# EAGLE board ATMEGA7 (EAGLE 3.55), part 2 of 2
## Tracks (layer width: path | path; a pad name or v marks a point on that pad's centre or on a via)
0V
  Top 0.33: JP4. 20.45,10.76 21.09,10.76 21.09,12.67 21.41,12.98 21.73,12.98 21.73,17.11 22.04,17.43 30.3,17.43 30.9,17.3
  Bottom 0.33: 30.9,17.3 30.93,16.48 34.11,16.48 35.05,16.35 35.38,15.53 35.38,14.26 42.36,14.26 42.68,14.57 42.68,17.43 45.85,17.43 46.65,17.3 46.81,16.48 49.98,16.48 50.8,16.35 51.25,15.53 51.25,14.26 58.24,14.26 58.55,14.57 58.55,17.43 61.73,17.43 62.35,17.3 62.37,16.48 65.54,16.48 66.5,16.35 66.81,15.53 66.81,14.26 74.11,14.26 74.43,14.57 74.43,17.43 77.29,17.43 78.12,17.3 78.24,16.48 81.42,16.48 82.28,16.35 82.69,15.53 82.69,14.26 89.67,14.26 89.99,14.57 89.99,17.43 93.16,17.43 93.88,17.3 93.8,16.48 97.29,16.48 98.03,16.35 98.56,15.53 98.56,14.26 105.55,14.26 105.86,14.57 105.86,17.43 109.04,17.43 109.6,17.3 109.67,16.48 112.85,16.48 113.75,16.35 114.12,15.53 114.12,14.26 121.42,14.26 121.74,14.57 121.74,17.43 124.59,17.43 125.4,17.3 125.55,16.48 128.72,16.48 129.55,16.35 129.99,15.53 129.99,14.57 130.31,14.26 136.66,14.26 136.66,17.11 136.98,17.43 140.47,17.43 141.1,17.3 141.1,16.48 144.28,16.48 145.25,16.35
+3V  (via drill 0.61 pad 1.02)
  Top 0.33: 53.16,40.92 53.79,41.24 53.79,52.67 54.11,52.99 54.43,52.99 54.43,53.94 54.11,54.26 54.11,54.58 53.79,54.9 53.79,55.85 53.16,56.16 53.16,56.8 53.16,65.69 55.7,65.69 56.42,65.96 | 38.55,31.4 38.55,29.18 38.6,28.33 | 38.55,31.4 v38.55,40.61 38.87,40.92 38.87,50.77 42.36,50.77 43,51.09 | 38.55,31.4 42.68,31.4 QG1. | 45.54,51.09 46.17,51.4 48.4,51.4 48.4,51.72 48.71,52.04 48.71,52.35 49.03,52.67 49.03,52.99 49.35,53.31 49.35,54.26 49.66,54.26 49.98,54.58 49.98,55.85 IC6. 50.62,56.8 v50.62,61.56
  Bottom 0.33: R10. 55.06,62.83 53.79,62.83 R11. 52.52,62.2 52.52,61.56 v50.62,61.56 34.74,61.56 34.42,61.24 34.42,57.75 34.45,56.7 34.42,55.85 33.79,55.85 | 33.79,55.85 33.79,53.94 29.34,53.94 29.34,51.72 29.66,51.4 35.38,51.4 35.38,49.5 36.97,49.5 38,49.66 | 33.79,55.85 33.65,56.7 | IC6. 53.16,56.16 | 43,51.09 45.54,51.09 45.85,50.45 56.33,50.45 56.65,50.13 57.6,50.13 57.92,49.81 58.87,49.81 58.87,50.13 59.19,50.45 60.46,50.45 60.78,51.09 | 53.24,31.33 52.52,30.77 52.52,30.13 46.49,30.13 46.17,30.45 46.17,31.08 43.95,31.08 QG1. | v38.55,40.61 36.01,40.61 R12.
+5V  (via drill 0.61 pad 1.02)
  Top 0.33: v26.17,13.94 26.49,13.62 26.49,12.67 26.8,12.35 v26.8,10.13
  Bottom 0.33: v26.17,13.94 25.85,14.26 20.14,14.26 20.14,13.62 19.68,12.98 | v26.8,10.13 28.39,10.13 29.03,10.06 29.66,10.13 31.25,10.13 R1. 32.52,10.13 34.42,10.13 34.74,9.81 35.38,9.81 35.7,10.13 43.95,10.13 44.59,10.06 45.22,10.13 46.81,10.13 R3. 48.08,10.13 49.98,10.13 50.3,9.81 51.25,9.81 51.57,10.13 59.83,10.13 60.46,10.06 61.09,10.13 62.37,10.13 R18. 63.64,10.13 65.86,10.13 66.17,9.81 66.81,9.81 67.13,10.13 75.7,10.13 76.33,10.06 76.97,10.13 78.24,10.13 R19. 79.51,9.81 82.69,9.81 83,10.13 91.58,10.13 92.21,10.06 92.84,10.13 94.11,10.13 R20. 95.39,10.13 97.29,10.13 97.61,9.81 98.56,9.81 98.88,10.13 107.13,10.13 107.77,10.06 108.4,10.13 109.67,10.13 R21. 110.94,10.13 112.85,10.13 113.17,9.81 114.12,9.81 114.44,10.13 123.01,10.13 123.64,10.06 124.28,10.13 125.55,10.13 R22. 126.82,9.81 129.99,9.81 130.31,10.13 138.88,10.13 139.52,10.06 140.15,10.13 141.42,10.13 R23.
+12V  (via drill 0.61 pad 1.02)
  Top 0.33: 112.85,80.18 112.21,79.66 112.21,79.98
  Top 0.406: 115.7,71.72 130.31,71.72 130.31,73.63 136.98,73.63 136.98,71.11 | 136.98,71.11 136.98,71.09 | 136.98,71.11 136.97,71.11
  Top 0.813: 112.85,79.98 112.21,79.98 109.67,79.98 109.67,80.3 115.7,80.3 115.7,71.72 50.94,71.72 | CON6. 10.93,80.3 v23.63,80.3 | v28.71,80.3 39.51,80.3 39.51,71.72 50.94,71.72 | 50.94,71.72 50.62,71.72
  Bottom 0.813: v23.63,80.3 v28.71,80.3
+15V
  Top 0.813: IC11. 95.7,84.42 103.32,84.42 JP5. 106.5,84.11 106.5,82.52 | 106.5,82.52 106.5,80.5 | 106.5,82.52 IC10.
-12V
  Top 0.33: 139.52,81.56 139.52,79.34 139.51,78.73
  Bottom 0.33: 153.48,77.46 153.17,76.8 140.15,76.8 139.84,77.12 139.84,78.07 139.51,78.73
A0  (via drill 0.61 pad 1.02)
  Top 0.33: v160.47,39.34 160.47,30.77 163.33,30.77 163.33,30.45 163.65,30.13 163.65,29.81 164.28,29.81 164.92,29.5 | v136.03,40.92 135.71,41.24 135.71,56.8 136.03,57.12 v136.66,57.12
  Bottom 0.33: 105.75,56.8 108.4,56.8 108.4,56.16 108.72,55.85 109.67,55.85 109.99,56.16 120.78,56.16 121.1,55.85 123.01,55.85 123.01,56.16 123.33,56.48 132.85,56.48 132.85,57.12 135.02,57.12 v136.66,57.12 | v160.47,39.34 160.16,39.66 137.93,39.66 137.61,39.97 137.61,40.92 v136.03,40.92
A1  (via drill 0.61 pad 1.02)
  Top 0.33: v139.52,32.35 v139.52,41.88 v139.52,52.35 | v103.96,55.85 106.18,55.85 v106.18,40.61
  Bottom 0.33: v139.52,52.35 136.34,52.35 136.03,52.67 133.8,52.67 133.49,52.99 132.22,52.99 132.22,55.53 132.53,55.85 135.02,55.85 | v139.52,32.35 139.84,32.67 161.11,32.67 161.43,32.99 161.43,33.3 163.01,33.3 163.33,32.99 163.65,32.99 163.97,32.67 164.6,32.67 164.92,32.03 | v103.96,55.85 103.96,55.53 105.75,55.53 | v106.18,40.61 106.5,40.29 134.75,40.29 135.07,40.61 135.07,41.88 v139.52,41.88
A2  (via drill 0.61 pad 1.02)
  Top 0.33: v138.56,54.58 v138.56,40.61 | v159.84,40.61 159.52,40.29 159.52,36.48 159.84,36.16 159.84,30.13 160.16,29.81 161.74,29.81 162.38,29.5 | v100.15,54.26 100.47,54.58 v100.47,63.15 | v120.78,63.78 v120.78,69.18 | v133.17,69.18 v133.17,54.58
  Bottom 0.33: v138.56,40.61 v159.84,40.61 | v138.56,54.58 135.02,54.58 v133.17,54.58 | v100.47,63.15 113.8,63.15 114.44,63.78 v120.78,63.78 | v120.78,69.18 v133.17,69.18 | v100.15,54.26 105.75,54.26
A3  (via drill 0.61 pad 1.02)
  Top 0.33: v136.66,53.31 136.66,41.56 136.98,41.24 136.98,39.97 v136.66,39.66 | v104.28,39.66 103.96,39.97 v103.96,52.67
  Bottom 0.33: v104.28,39.66 v136.66,39.66 | v103.96,52.67 103.96,52.99 105.75,52.99 | v136.66,53.31 135.02,53.31
A4  (via drill 0.61 pad 1.02)
  Top 0.33: v131.9,66.33 v131.9,52.04 | v102.05,64.1 102.05,53.31 101.73,52.99 101.73,51.72 v102.05,51.4
  Bottom 0.33: v131.9,66.33 115.7,66.33 115.39,66.01 115.39,65.37 115.07,65.37 114.75,65.06 114.75,64.42 114.12,64.42 113.8,64.1 113.48,64.1 113.17,63.78 102.37,63.78 v102.05,64.1 | v102.05,51.4 102.37,51.72 105.75,51.72 | v131.9,52.04 135.02,52.04
A5  (via drill 0.61 pad 1.02)
  Top 0.33: v129.36,67.28 v129.36,50.77 | v101.1,65.06 101.1,63.78 101.42,63.47 101.42,57.12 101.1,56.8 v101.1,50.45
  Bottom 0.33: v129.36,67.28 129.04,66.96 115.07,66.96 114.75,66.64 114.75,66.01 114.12,65.37 113.8,65.37 113.8,65.06 113.48,64.74 113.17,64.74 112.85,64.42 103,64.42 102.69,64.74 102.69,65.06 v101.1,65.06 | v129.36,50.77 135.02,50.77 | v101.1,50.45 105.75,50.45
A6  (via drill 0.61 pad 1.02)
  Top 0.33: v131.58,43.47 v131.58,49.5 | v121.42,46.96 v121.42,43.15
  Bottom 0.33: v131.58,43.47 123.01,43.47 122.69,43.15 v121.42,43.15 | v121.42,46.96 116.66,46.96 116.34,47.27 103.96,47.27 103.64,47.59 103.64,49.18 105.75,49.18 | v131.58,49.5 135.02,49.5
A7  (via drill 0.61 pad 1.02)
  Top 0.33: v118.88,50.13 v118.88,45.69
  Bottom 0.33: v118.88,45.69 127.45,45.69 127.45,46.64 127.77,46.96 132.85,46.96 132.85,48.23 135.02,48.23 | v118.88,50.13 114.75,50.13 114.44,49.81 110.31,49.81 109.99,49.5 109.99,47.91 105.75,47.91
A8  (via drill 0.61 pad 1.02)
  Top 0.33: v117.93,38.7 v117.93,49.18
  Bottom 0.33: v117.93,38.7 102.05,38.7 102.05,39.97 100.47,39.97 100.21,39.93 | v117.93,49.18 113.02,49.18
A9  (via drill 0.61 pad 1.02)
  Top 0.33: v86.5,39.34 v86.5,47.59
  Bottom 0.33: v86.5,39.34 87.77,39.34 88.08,39.02 99.83,39.02 100.21,39.13 | v86.5,47.59 102.69,47.59 103,47.91 103,49.81 109.36,49.81 109.67,50.13 109.67,50.45 113.02,50.45
A10  (via drill 0.61 pad 1.02)
  Top 0.33: v87.45,46.32 v87.45,38.38 | v80.14,46.32 v80.14,52.99
  Bottom 0.33: v87.45,38.38 99.83,38.38 100.21,38.33 | v80.14,46.32 v87.45,46.32 | v80.14,52.99 80.46,52.67 93.8,52.67 94.11,52.99 94.75,52.99 95.07,53.31 102.05,53.31 102.37,53.62 109.36,53.62 109.67,53.94 109.67,54.26 113.02,54.26
A11  (via drill 0.61 pad 1.02)
  Top 0.33: v92.84,37.43 92.84,26.95 93.16,26.64 v93.16,24.41 | v119.83,24.1 119.83,50.77 119.52,51.09 v117.93,51.09
  Bottom 0.33: v92.84,37.43 99.83,37.43 100.21,37.53 | v93.16,24.41 95.07,24.41 95.39,24.1 v119.83,24.1 | v117.93,51.09 114.12,51.09 113.8,51.4 113.8,51.72 113.02,51.72
A12  (via drill 0.61 pad 1.02)
  Top 0.33: v103,46.64 103.32,46.32 v103.32,36.8
  Bottom 0.33: 100.21,36.73 100.47,36.8 v103.32,36.8 115.7,36.8 115.7,35.01 | v103,46.64 105.75,46.64
A13  (via drill 0.61 pad 1.02)
  Top 0.33: v116.97,36.8 v116.97,47.91
  Bottom 0.33: 100.21,35.93 100.47,35.84 101.42,35.84 101.73,36.16 102.37,36.16 102.69,35.84 113.8,35.84 114.12,35.53 114.12,34.58 114.44,34.58 114.75,34.26 114.75,33.62 116.97,33.62 116.97,35.01 v116.97,36.8 | v116.97,47.91 113.02,47.91
A14  (via drill 0.61 pad 1.02)
  Top 0.33: v102.05,35.21 v102.05,37.75 102.05,42.83 102.37,43.15 v102.37,45.37
  Bottom 0.33: v102.05,35.21 100.47,35.21 100.21,35.13 | v102.37,45.37 105.75,45.37 | v102.05,37.75 118.25,37.75 118.25,35.01
A15  (via drill 0.61 pad 1.02)
  Top 0.33: v103.32,34.58 102.69,34.58 102.37,34.26 101.1,34.26 101.1,43.15 v101.42,43.47 | v141.42,37.11 141.42,31.72 141.1,31.4 136.98,31.4 136.98,36.16 136.66,36.48 136.66,36.8 135.07,36.8 v135.07,38.7 | v122.37,44.1 v122.37,38.7
  Bottom 0.33: v103.32,34.58 103,34.26 100.47,34.26 100.21,34.33 | v101.42,43.47 109.36,43.47 109.67,43.78 109.67,44.1 113.02,44.1 v122.37,44.1 | v141.42,37.11 150.95,37.11 150.95,35.15 | v122.37,38.7 v135.07,38.7
A16  (via drill 0.61 pad 1.02)
  Top 0.33: v140.47,46.96 v140.47,35.84
  Bottom 0.33: 147.14,35.15 147.14,34.58 145.87,34.58 145.87,35.15 145.87,35.84 v140.47,35.84 | 97.41,43.53 97.61,43.78 97.61,44.42 99.51,44.42 99.83,44.73 101.73,44.73 102.05,44.42 102.37,44.42 102.69,44.1 105.75,44.1 109.04,44.1 109.04,44.42 109.36,44.73 119.2,44.73 119.52,45.05 127.77,45.05 128.09,45.37 128.09,46.01 128.41,46.32 136.66,46.32 137.29,46.96 v140.47,46.96
AD0  (via drill 0.61 pad 1.02)
  Top 0.33: v97.61,30.45 97.92,30.77 97.92,54.26 97.61,54.58 97.61,57.44 v97.29,57.75 | v168.09,59.02 167.78,58.7 v167.78,52.35 | v151.58,57.12 153.22,57.12 | v156.98,57.12 v156.98,53.62 | v103.96,58.07 v103.96,65.37 | v113.8,66.33 116.97,66.33 116.97,62.52 116.66,62.2 v116.66,59.02
  Bottom 0.33: v97.61,30.45 96.66,30.45 96.66,27.91 96.61,27.53 | v97.29,57.75 97.61,58.07 v103.96,58.07 105.75,58.07 | v168.09,59.02 168.41,58.7 175.08,58.7 175.08,59.02 175.4,59.34 176.35,59.34 176.66,59.98 | v167.78,52.35 164.92,52.35 164.6,52.99 163.65,52.99 163.33,53.31 163.33,53.62 v156.98,53.62 | v156.98,57.12 153.44,57.12 v151.58,57.12 150.31,57.12 150.31,57.44 150,57.75 142.69,57.75 142.38,58.07 141.74,58.07 141.74,58.7 141.42,59.02 136.03,59.02 136.03,57.75 132.22,57.75 132.22,57.44 131.9,57.12 125.5,57.12 123.33,57.12 123.33,58.7 123.01,59.02 v116.66,59.02 | v103.96,65.37 104.28,65.06 112.53,65.06 112.85,65.37 113.17,65.37 113.17,66.33 v113.8,66.33
AD1  (via drill 0.61 pad 1.02)
  Top 0.33: v151.58,55.85 153.22,55.85 | v166.19,60.93 166.19,56.8 165.87,56.48 165.87,55.85 165.55,55.53 165.55,55.21 164.92,54.9 | v98.24,29.18 98.56,29.5 98.56,54.58 98.24,54.9 v98.24,59.34 | v126.5,32.35 126.5,55.53 v127.14,55.53 127.45,55.85 v127.45,58.7 | v145.87,56.16 145.55,56.48 145.55,59.34 145.23,59.66 v142.06,59.66
  Bottom 0.33: v166.19,60.93 166.5,60.61 173.81,60.61 174.12,59.98 | 164.92,54.9 164.6,55.53 163.97,55.53 163.65,55.85 163.33,55.85 163.01,56.16 161.74,56.16 161.43,55.85 153.44,55.85 v151.58,55.85 151.26,56.16 v145.87,56.16 | v98.24,29.18 97.29,29.18 97.29,27.91 97.41,27.53 97.29,27.27 97.29,26.64 113.8,26.64 113.8,31.72 114.12,32.03 126.18,32.03 v126.5,32.35 | v98.24,59.34 105.75,59.34 | v127.14,55.53 127.14,55.85 125.5,55.85 | v142.06,59.66 130.94,59.66 130.63,59.34 130.63,58.7 v127.45,58.7
AD2  (via drill 0.61 pad 1.02)
  Top 0.33: 153.22,54.58 v151.58,54.58 150.63,54.58 v150.63,65.37 | v160.47,54.58 v160.47,58.7 | v99.19,60.61 v99.19,55.21 v99.19,27.91 | v130.31,54.58 v130.31,65.37
  Bottom 0.33: v151.58,54.58 153.44,54.58 v160.47,54.58 | 176.66,57.44 176.35,56.8 175.4,56.8 175.08,56.48 175.08,56.16 173.49,56.16 173.17,56.48 172.54,56.48 172.22,56.8 165.24,56.8 164.92,57.44 164.6,58.07 163.97,58.07 163.65,58.39 163.33,58.39 163.01,58.7 v160.47,58.7 | v99.19,27.91 98.24,27.91 98.21,27.53 | v99.19,60.61 105.75,60.61 | v99.19,55.21 100.47,55.21 100.78,54.9 115.07,54.9 115.07,54.58 115.39,54.26 120.78,54.26 121.1,54.58 125.5,54.58 v130.31,54.58 | v130.31,65.37 v150.63,65.37
AD3  (via drill 0.61 pad 1.02)
  Top 0.33: v151.58,53.31 153.22,53.31 | v155.71,53.31 v155.71,61.24 v155.71,64.74 | v111.26,61.88 v111.26,53.31 v111.26,29.5 | v116.02,64.74 115.7,64.42 v115.7,61.88
  Bottom 0.33: v151.58,53.31 153.44,53.31 v155.71,53.31 | 174.12,57.44 173.81,58.07 167.46,58.07 167.14,58.39 167.14,59.98 164.92,59.98 164.6,60.61 163.97,60.61 163.65,60.93 163.33,60.93 163.01,61.24 v155.71,61.24 | v111.26,29.5 100.47,29.5 100.21,29.53 | v111.26,61.88 IC7. v115.7,61.88 | v111.26,53.31 111.58,53.62 115.39,53.62 115.7,53.31 125.5,53.31 | v155.71,64.74 155.39,64.42 124.28,64.42 123.96,64.74 v116.02,64.74
AD4  (via drill 0.61 pad 1.02)
  Top 0.33: v151.58,52.04 153.22,52.04 | 164.92,62.52 164.28,62.2 164.28,61.24 163.97,60.93 163.65,60.93 v163.65,51.09 161.11,51.09 161.11,48.86 160.79,48.55 159.52,48.55 159.52,42.83 159.2,42.51 v158.25,42.51 | v107.13,30.45 107.45,30.77 v107.45,52.35 v107.45,60.61 | v130.63,52.04 v130.63,42.51
  Bottom 0.33: v151.58,52.04 153.44,52.04 156.34,52.04 156.66,51.72 160.47,51.72 160.79,51.4 161.43,51.4 161.74,51.09 v163.65,51.09 168.73,51.09 168.73,53.31 169.04,53.62 175.08,53.62 175.08,53.94 175.4,54.26 176.35,54.26 176.66,54.9 | v107.13,30.45 100.47,30.45 100.21,30.33 | v107.45,60.61 113.02,60.61 | v107.45,52.35 114.44,52.35 114.75,52.04 125.5,52.04 v130.63,52.04 | v158.25,42.51 157.93,42.83 133.49,42.83 133.17,42.51 v130.63,42.51
AD5  (via drill 0.61 pad 1.02)
  Top 0.33: v155.39,50.77 153.22,50.77 | v159.52,63.78 v159.52,50.77 | v108.4,31.08 108.4,32.99 108.72,33.3 108.72,56.16 108.4,56.48 v108.4,59.34 | v123.33,50.77 v123.33,59.98 123.64,60.29 v123.64,63.78
  Bottom 0.33: 153.44,50.77 v155.39,50.77 v159.52,50.77 | 174.12,54.9 174.44,55.53 175.4,55.53 175.71,55.85 175.71,56.16 177.3,56.16 177.62,56.48 178.25,56.48 178.57,56.8 178.57,63.78 173.49,63.78 173.17,64.1 172.54,64.1 172.22,64.42 165.24,64.42 164.92,65.06 164.6,64.42 163.97,64.42 163.65,64.1 163.33,64.1 163.01,63.78 v159.52,63.78 v123.64,63.78 | v108.4,31.08 108.08,31.4 106.81,31.4 106.5,31.08 100.47,31.08 100.21,31.13 | v108.4,59.34 113.02,59.34 115.7,59.34 115.7,59.66 116.02,59.98 v123.33,59.98 | v123.33,50.77 125.5,50.77
AD6  (via drill 0.61 pad 1.02)
  Top 0.33: v151.58,49.5 153.22,49.5 | v157.3,66.33 155.07,66.33 154.76,66.01 154.76,60.93 155.07,60.61 155.07,53.94 154.76,53.62 154.76,51.4 152.22,51.4 151.9,51.09 151.9,49.81 v151.58,49.5 | v110.31,31.72 v110.31,58.07 | v121.42,58.07 v121.42,49.5 | v150.31,45.37 150.63,45.69 150.63,49.5 v151.58,49.5 | v129.68,49.5 v129.68,45.37
  Bottom 0.33: v151.58,49.5 153.44,49.5 | 176.66,52.35 176.98,52.99 178.89,52.99 179.21,53.31 179.21,66.33 173.49,66.33 173.17,66.64 172.54,66.64 172.22,66.96 165.24,66.96 164.92,67.59 164.6,66.96 163.97,66.96 163.65,66.64 163.33,66.64 163.01,66.33 v157.3,66.33 | v110.31,31.72 109.04,31.72 108.72,32.03 100.47,32.03 100.21,31.93 | v110.31,58.07 113.02,58.07 v121.42,58.07 | v121.42,49.5 125.5,49.5 v129.68,49.5 | v150.31,45.37 150,45.05 129.99,45.05 v129.68,45.37
AD7  (via drill 0.61 pad 1.02)
  Top 0.33: 153.22,48.23 v151.58,48.23 151.26,47.91 v151.26,44.42 | v170.95,70.14 v170.95,52.35 | v158.57,48.23 158.57,57.44 158.88,57.75 158.88,63.15 158.57,63.47 v158.57,68.87 | v109.36,32.67 v109.36,56.8 | v122.37,56.8 v122.37,48.23 | v128.72,48.23 v128.72,44.42
  Bottom 0.33: v151.58,48.23 153.44,48.23 v158.57,48.23 | v170.95,52.35 174.12,52.35 | v170.95,70.14 164.92,70.14 164.6,69.5 163.97,69.5 163.65,69.18 163.33,69.18 163.01,68.87 v158.57,68.87 | v109.36,32.67 100.47,32.67 100.21,32.73 | v109.36,56.8 113.02,56.8 v122.37,56.8 | v122.37,48.23 125.5,48.23 v128.72,48.23 | v128.72,44.42 v151.26,44.42
CLKI  (via drill 0.61 pad 1.02)
  Top 0.33: v30.3,52.99 30.3,32.35 29.03,32.35 28.27,31.89
  Bottom 0.33: 58.24,53.62 57.92,52.99 57.6,52.99 57.6,52.04 57.28,51.72 46.81,51.72 46.81,53.94 46.49,54.26 46.49,54.58 46.17,54.58 45.85,54.9 40.46,54.9 40.46,53.62 38.87,53.62 38,53.66 36.97,53.62 34.42,53.62 34.11,53.31 30.61,53.31 v30.3,52.99
DEMAND  (via drill 0.61 pad 1.02)
  Top 0.33: v79.19,35.53 79.19,28.54 v78.88,28.23 | v53.16,29.5 49.03,29.5 49.03,36.16 48.71,36.48 41.09,36.48 41.09,47.91 41.41,48.23 42.36,48.23 43,48.55
  Bottom 0.33: v79.19,35.53 79.51,35.84 83.95,35.84 84.21,35.93 | v78.88,28.23 78.56,27.91 75.7,27.91 75.38,28.23 74.75,28.23 74.43,28.54 74.11,28.54 74.11,29.5 v53.16,29.5
GND  (via drill 0.61 pad 1.02)
  Top 0.33: v143.65,34.89 v143.65,41.56 | CON3. 161.74,24.73 159.2,24.73 159.2,35.53 v158.88,35.84 158.88,41.56 159.2,41.88 161.74,41.88 162.38,42.2 162.38,42.83 162.38,44.1 162.38,44.73 162.38,45.37 162.38,46.64 162.38,47.27 | 153.22,58.39 153.49,58.39 153.49,71.72 153.48,72.38 | v139.52,61.24 139.52,70.45 139.51,71.11 138.88,71.41 138.88,76.8 138.56,77.12 | 138.56,77.12 138.56,78.07 138.25,78.39 138.25,84.11 139.52,84.11 | v169.04,49.81 169.04,74.26 168.73,74.58 162.38,74.58 162.38,73.31 162.38,72.67 | 26.07,40.28 26.17,39.66 26.17,25.05 26.49,24.73 27.44,24.73 28.27,24.27 28.39,25.05 28.39,27.59 35.38,27.59 C18. | 53.16,38.38 52.52,38.7 52.52,39.97 52.2,40.29 51.89,40.29 51.89,41.24 51.57,41.56 51.57,42.51 51.25,42.83 51.25,53.62 50.62,53.62 | v55.7,34.26 55.7,37.75 55.7,38.38 | 45.54,56.16 44.9,55.85 43.95,55.85 43.63,55.53 43.63,53.94 43,53.62 43,54.26 43,68.87 | 76.33,41.88 76.97,42.2 77.61,42.2 77.61,47.27 77.29,47.59 77.29,49.18 76.97,49.5 76.33,49.5 | v93.8,39.97 v93.8,29.18 | v123.96,36.48 v123.96,46.96 124.28,47.27 124.28,61.88 v124.59,62.2 124.59,64.42 124.28,64.74 122.69,64.74 122.69,61.24 122.37,60.93 119.52,60.93 119.52,68.23 119.2,68.55 118.25,68.87 | CON1. 1.09,39.34 1.09,51.72 CON2. 2.36,53.31 4.9,53.31 4.9,68.23 5.21,68.55 5.85,68.55 6.8,68.87 | 31.25,60.6 31.25,63.78 31.57,64.1 31.57,68.87 | 86.5,68.87 86.5,62.52 86.18,62.52 85.86,62.2 85.86,61.24 85.22,60.93 85.86,60.61 85.86,60.29 86.18,60.29 86.5,59.98 86.5,59.02 86.18,58.7 86.18,50.77 v86.5,50.45 | 58.24,56.16 58.24,56.8 58.24,63.78 58.55,64.1 58.55,68.87 | 138.56,77.12 138.25,76.8 118.25,76.8
  Top 0.406: 21.09,53.62 21.09,70.14
  Top 0.813: 78.56,84.42 81.1,84.42 83.64,84.42 | 78.56,84.42 76.02,84.42 76.02,82.52 70.94,82.52 70.94,84.42 67.44,84.42 D1. | 78.56,84.42 78.56,79.98 | 78.56,79.98 78.56,76.8 | 78.56,79.98 C14. 95.39,79.98 | 103.32,79.34 95.7,79.34 | 103.32,79.34 103.32,81.56 | 103.32,79.34 103.32,77.55 C28. 109.67,77.55 109.67,77.44 112.85,77.44 C29. | 36.33,77.75 36.33,70.14 21.09,70.14 21.09,75.22 16.01,75.22 15.69,75.22
  Top 1.016: C29. 112.85,73.63 v113.17,73.63
  Bottom 0.33: v143.65,34.89 138.56,34.89 138.56,35.15 | v143.65,41.56 162.06,41.56 162.38,42.2 | v158.88,35.84 153.49,35.84 153.49,35.15 | 162.38,47.27 162.69,47.91 163.33,47.91 163.33,48.86 163.65,49.18 164.6,49.18 164.92,49.81 v169.04,49.81 | 139.52,84.11 144.6,84.11 | 176.66,72.67 174.12,72.67 173.81,73.31 166.19,73.31 165.87,73.63 165.87,73.94 164.28,73.94 163.97,73.63 163.33,73.63 163.01,73.31 162.69,73.31 162.38,72.67 156.98,72.67 156.66,72.36 154.12,72.36 153.48,72.38 152.85,72.99 144.28,72.99 144.28,72.36 143.96,72.04 142.69,72.04 142.38,72.36 139.84,72.36 139.84,71.72 139.51,71.11 | 143.91,58.39 143.65,58.39 143.65,59.66 C5. 143.33,61.24 v139.52,61.24 | JP3. 19.82,25.05 19.82,24.41 27.44,24.41 28.27,24.27 | 40.77,50.45 38.87,50.45 38,50.45 | 40.77,50.45 41.09,50.77 41.09,53.62 43,53.62 | 41.41,50.13 42.36,50.13 42.68,49.81 43.63,49.81 43.63,49.5 43.95,49.18 45.22,49.18 45.54,48.55 | 41.41,50.13 41.09,50.45 40.77,50.45 | 41.41,50.13 40.46,50.13 40.46,47.27 38.87,47.27 38,47.26 36.97,47.27 32.2,47.27 32.2,45.05 32.05,44.2 32.2,43.15 32.2,42.83 31.88,42.51 31.57,42.51 31.57,42.2 31.25,41.88 26.49,41.88 26.49,40.61 26.07,40.28 | 52.2,32.35 51.25,32.35 51.25,31.72 50.62,31.2 | 52.2,32.35 52.52,32.67 52.52,33.94 C21. 53.79,34.26 v55.7,34.26 | 52.2,32.35 57.6,32.35 57.6,31.72 58.24,31.2 | 53.16,38.38 55.7,38.38 | 50.62,53.62 50.62,54.26 49.03,54.26 48.71,54.58 48.71,54.9 47.76,54.9 47.44,55.21 47.12,55.21 46.81,55.53 45.85,55.53 45.54,56.16 | 67.65,40.93 67.76,41.56 67.76,42.83 67.65,43.47 67.76,44.1 67.76,44.73 | 67.76,44.73 67.76,45.05 67.65,45.69 67.76,46.32 67.76,47.27 67.65,47.91 67.76,48.55 67.76,49.5
  Bottom 0.33: 67.76,49.5 76.33,49.5 | v93.8,29.18 95.07,29.18 95.07,27.91 95.01,27.53 | v93.8,39.97 93.48,40.29 90.62,40.29 90.31,40.61 90.31,43.15 90.21,43.53 90.31,43.78 90.31,44.42 81.42,44.42 81.1,44.73 79.83,44.73 C8. 78.24,44.42 74.11,44.42 C10. 72.53,44.73 67.76,44.73 | 125.5,58.39 125.86,58.39 125.86,59.66 C9. 125.86,61.24 125.86,62.2 v124.59,62.2 | 120.78,34.26 119.52,34.26 119.52,35.01 | v123.96,36.48 124.28,36.48 124.59,36.16 124.59,35.01 124.59,32.99 120.78,32.99 120.78,34.26 | v123.96,46.96 125.5,46.96 | 120.78,34.26 120.78,35.01 | 28.07,55.85 28.07,54.58 25.54,54.58 24.5,54.45 | 28.07,55.85 28.71,55.85 28.85,56.7 28.71,57.75 28.71,59.34 29.03,59.34 29.34,59.66 30.93,59.66 31.25,59.98 31.25,60.6 | 28.07,55.85 28.05,56.7 | 58.24,56.16 60.46,56.16 60.46,54.26 60.78,53.62 61.09,52.99 62.37,52.99 62.68,52.67 62.68,50.77 63,50.45 67.76,50.45 67.76,49.5 | C2. 90.94,50.45 89.99,50.45 C3. 88.72,50.45 v86.5,50.45 | 105.75,61.88 99.83,61.88 99.51,62.2 99.51,68.87 | C1. 105.55,67.91 105.89,68.87
  Bottom 0.406: 1.41,52.7 1.41,52.67 | 1.73,62.13 1.41,62.13 1.41,52.7 | CON2. 1.41,52.7 | 1.41,52.7 1.41,38.38
  Bottom 0.813: 95.7,79.34 95.39,79.03
  Bottom 1.016: v113.17,73.63 113.17,71.72 36.33,71.72 36.33,77.75
  pour Bottom (isolate 0.762): 6.8,86.96 118.25,86.96 118.25,68.87 6.8,68.87
  pour Top (isolate 0.762): 118.25,68.87 6.8,68.87 6.8,86.64 118.25,86.64
IDE_CSHI
  Bottom 0.33: 128.41,31.4 129.36,31.4 129.68,31.72 132.22,31.72 132.22,29.69 | 128.41,31.4 116.97,31.4 116.97,29.5 | 128.41,31.4 128.41,36.8 128.72,37.11 134.75,37.11 134.75,35.15
IDE_CSLO  (via drill 0.61 pad 1.02)
  Top 0.33: v129.36,34.58 v129.36,30.45 129.68,30.77 129.68,31.4 v134.44,31.4 134.75,31.08 v134.75,24.41
  Bottom 0.33: v129.36,30.45 129.04,30.77 118.25,30.77 118.25,29.5 | v129.36,34.58 130.94,34.58 130.94,35.15 | v134.44,31.4 134.75,31.08 135.39,31.08 135.71,30.77 136.03,30.77 136.03,29.69 | v134.75,24.41 160.16,24.41 160.16,23.78 160.47,23.78 160.79,23.46 161.43,23.46 161.74,23.14 168.09,23.14 168.09,26.64 167.78,26.95 164.92,26.95
IDE_D8  (via drill 0.61 pad 1.02)
  Top 0.33: v142.06,57.12 143.7,57.12 | v137.61,58.07 v137.61,69.18
  Bottom 0.33: 143.91,57.12 v142.06,57.12 141.74,57.44 137.61,57.44 v137.61,58.07 | v137.61,69.18 138.88,69.18 139.2,68.87 141.1,68.87 141.42,68.55 155.39,68.55 155.39,69.82 155.71,70.14 162.38,70.14
IDE_D9  (via drill 0.61 pad 1.02)
  Top 0.33: v142.06,55.85 143.7,55.85 | v138.56,55.85 v138.56,68.23
  Bottom 0.33: 143.91,55.85 v142.06,55.85 v138.56,55.85 | v138.56,68.23 140.79,68.23 141.1,67.91 146.19,67.91 146.5,67.59 162.38,67.59
IDE_D10  (via drill 0.61 pad 1.02)
  Top 0.33: v142.06,54.58 143.7,54.58 | v140.47,67.28 140.47,54.9 v140.15,54.58
  Bottom 0.33: 143.91,54.58 v142.06,54.58 v140.15,54.58 | v140.47,67.28 145.87,67.28 146.19,66.96 156.34,66.96 156.34,65.37 156.66,65.06 162.38,65.06
IDE_D11  (via drill 0.61 pad 1.02)
  Top 0.33: v142.06,53.31 143.7,53.31 146.82,53.31 146.82,56.48 146.5,56.8 146.5,66.33 151.26,66.33 151.58,66.64 151.58,74.58 153.81,74.58 154.12,74.26 154.12,73.94 154.44,73.63 154.44,73.31 154.76,72.99 160.16,72.99 160.47,72.67 160.47,63.15 160.79,63.15 161.11,62.83 161.74,62.83 162.38,62.52
  Bottom 0.33: v142.06,53.31 143.91,53.31
IDE_D12  (via drill 0.61 pad 1.02)
  Top 0.33: v142.06,52.04 143.7,52.04 147.14,52.04 147.46,52.35 147.46,56.8 147.14,57.12 147.14,61.88 v147.46,62.2 | v160.47,62.2 160.47,60.93 161.43,60.93 161.74,60.61 161.74,60.29 162.38,59.98
  Bottom 0.33: v142.06,52.04 143.91,52.04 | v147.46,62.2 v160.47,62.2
IDE_D13  (via drill 0.61 pad 1.02)
  Top 0.33: v142.06,50.77 143.7,50.77 146.19,50.77 146.5,50.45 146.5,29.81 154.76,29.81 155.07,30.13 155.07,48.23 157.62,48.23 157.62,48.55 157.93,48.86 v157.93,58.07
  Bottom 0.33: v142.06,50.77 143.91,50.77 | v157.93,58.07 157.93,57.75 158.25,57.44 162.38,57.44
IDE_D14  (via drill 0.61 pad 1.02)
  Top 0.33: 143.7,49.5 v142.06,49.5 | v160.79,59.98 161.11,59.66 161.11,59.34 161.43,59.02 161.43,58.39 161.11,58.07 161.11,55.21 161.74,55.21 162.38,54.9 | v149.04,49.5 v149.04,59.98
  Bottom 0.33: v142.06,49.5 143.91,49.5 v149.04,49.5 | v149.04,59.98 v160.79,59.98
IDE_D15  (via drill 0.61 pad 1.02)
  Top 0.33: 143.7,48.23 v142.06,48.23 | v160.16,49.5 160.47,49.81 160.47,52.04 161.74,52.04 162.38,52.35
  Bottom 0.33: v142.06,48.23 143.91,48.23 150,48.23 150,50.13 150.31,50.45 151.9,50.45 152.22,50.13 154.44,50.13 154.76,49.81 159.84,49.81 v160.16,49.5
LCD_CD  (via drill 0.61 pad 1.02)
  Top 0.33: v90.31,46.64 90.31,58.7 90.62,59.02 91.58,59.02 91.58,64.1 91.89,64.42 91.89,65.06 92.21,65.37 92.21,65.69 96.34,65.69 96.34,66.96 96.66,67.28 v110.62,67.28 | v145.55,66.33 145.87,66.64 145.87,66.96 150.95,66.96 150.95,75.22 151.26,75.53 154.76,75.53 155.07,75.85 155.07,76.17 155.39,76.48 155.39,76.8 155.71,77.12 171.9,77.12 171.9,65.69 172.22,65.37 173.49,65.37 174.12,65.06
  Bottom 0.33: v90.31,46.64 93.48,46.64 93.48,43.78 93.41,43.53 | v110.62,67.28 110.94,67.59 120.15,67.59 120.47,67.91 128.72,67.91 129.04,68.23 137.29,68.23 137.61,67.91 137.61,66.33 v145.55,66.33
LCD_CS  (via drill 0.61 pad 1.02)
  Top 0.33: v96.66,34.58 v96.66,25.68 | v108.4,25.68 109.36,25.68 109.36,24.41 109.67,24.1 116.66,24.1 v116.66,26.64 | v143.65,26.95 143.96,26.64 143.96,23.46 144.28,23.14 172.22,23.14 172.22,63.47 172.54,63.78 176.03,63.78 176.03,64.74 176.66,65.06
  Bottom 0.33: v96.66,34.58 96.34,34.26 84.59,34.26 84.21,34.33 | v96.66,25.68 v108.4,25.68 | v116.66,26.64 116.97,26.95 121.42,26.95 121.74,27.27 122.69,27.27 123.01,26.95 v143.65,26.95
LCDLIGHT  (via drill 0.61 pad 1.02)
  Top 0.33: v80.46,34.89 80.46,29.18 80.78,28.86 81.1,28.86 81.1,26.95 80.78,26.64 62.68,26.64 62.68,56.8 62.37,57.12 62.05,57.12 v62.05,63.78
  Bottom 0.33: v80.46,34.89 80.78,35.21 83.95,35.21 84.21,35.13 | v62.05,63.78 49.03,63.78 48.71,63.47 48.71,63.15 9.34,63.15 9.34,62.83 9.23,62.2
LPTACK  (via drill 0.61 pad 1.02)
  Top 0.33: v78.24,32.03 78.24,56.8 77.92,57.12 75.06,57.12 75.06,57.75 | 75.06,57.75 75.06,60.93 | 75.06,57.75 v73.16,57.75
  Bottom 0.33: v78.24,32.03 83.95,32.03 84.21,31.93 | v73.16,57.75 74.43,57.75 75.06,57.64
LPTCLK  (via drill 0.61 pad 1.02)
  Top 0.33: v100.15,52.04 v100.15,43.78 | v63,57.75 63,63.15 64.27,63.15 64.91,63.47
  Bottom 0.33: v100.15,43.78 98.24,43.78 98.21,43.53 | v100.15,52.04 69.03,52.04 68.72,52.35 68.4,52.35 68.4,52.99 63.32,52.99 63,53.31 v63,57.75 64.27,57.75 64.91,57.64
LPTD0  (via drill 0.61 pad 1.02)
  Top 0.33: v64.91,34.58 64.91,60.93
  Bottom 0.33: v64.91,34.58 75.06,34.58 75.06,35.21 75.38,35.21 75.7,35.53 78.24,35.53 78.24,36.16 78.56,36.48 81.73,36.48 82.05,36.8 83.95,36.8 84.21,36.73
LPTD1  (via drill 0.61 pad 1.02)
  Top 0.33: v81.42,32.99 v81.42,37.43 | 76.33,34.26 75.7,33.94 75.38,33.62 75.38,33.3 v75.06,32.99 74.75,32.67 73.8,32.67 73.48,32.35 73.48,27.59 68.72,27.59 68.4,27.91 68.4,46.64 68.72,46.96 68.72,61.88 68.4,61.88 68.08,62.2 68.08,63.15 67.44,63.47
  Bottom 0.33: v81.42,37.43 83.95,37.43 84.21,37.53 | v75.06,32.99 v81.42,32.99
LPTD2  (via drill 0.61 pad 1.02)
  Top 0.33: v85.54,38.38 83.95,38.38 83.95,44.73 83.64,45.05 83.64,49.81 83.95,50.13 83.95,50.45 v84.27,50.77 | v67.44,51.4 67.44,60.93
  Bottom 0.33: v85.54,38.38 84.59,38.38 84.21,38.33 | v84.27,50.77 84.27,51.4 v67.44,51.4
LPTD3  (via drill 0.61 pad 1.02)
  Top 0.33: v81.1,39.02 81.1,42.83 81.42,43.15 81.73,43.15 81.73,47.59 81.42,47.91 81.1,47.91 81.1,55.53 81.42,55.85 83.95,55.85 83.95,64.1 83.64,64.42 83.64,65.06 83.32,65.37 83.32,65.69 82.37,65.69 82.37,66.96 82.05,67.28 69.98,67.28 69.98,63.47
  Bottom 0.33: v81.1,39.02 83.95,39.02 84.21,39.13
LPTD4  (via drill 0.61 pad 1.02)
  Top 0.33: v82.05,39.97 82.05,42.51 82.37,42.83 82.37,48.23 v82.05,48.55 | v69.98,48.23 69.98,60.93
  Bottom 0.33: v82.05,39.97 83.95,39.97 84.21,39.93 | v82.05,48.55 81.73,48.23 v69.98,48.23
LPTD5  (via drill 0.61 pad 1.02)
  Top 0.33: v85.54,40.61 v85.54,59.34
  Bottom 0.33: v85.54,40.61 84.59,40.61 84.21,40.73 | v85.54,59.34 85.22,59.02 80.46,59.02 80.14,59.34 74.43,59.34 74.11,59.66 74.11,59.98 73.8,60.29 73.8,62.83 72.84,62.83 72.53,63.47
LPTD6  (via drill 0.61 pad 1.02)
  Top 0.33: v83,50.45 v83,41.24 | v72.21,50.45 72.21,58.07 72.53,58.39 72.53,60.93
  Bottom 0.33: v83,41.24 83.32,41.56 83.95,41.56 84.21,41.53 | v83,50.45 82.69,50.77 76.02,50.77 75.7,50.45 v72.21,50.45
LPTD7  (via drill 0.61 pad 1.02)
  Top 0.33: v80.78,43.78 78.88,43.78 78.88,57.12 78.56,57.44 78.56,57.75 76.33,57.75 76.33,61.56 76.02,61.88 76.02,62.2 75.7,62.52 75.7,63.15 75.06,63.47
  Bottom 0.33: v80.78,43.78 86.18,43.78 86.21,43.53
LPTHALT  (via drill 0.61 pad 1.02)
  Top 0.33: v91.26,57.75 v91.26,45.69 | v79.51,57.75 79.51,59.02 79.19,59.34 79.19,59.98 78.88,60.29 78.88,61.88 78.56,61.88 78.24,62.2 78.24,63.15 77.61,63.47
  Bottom 0.33: v91.26,45.69 92.53,45.69 92.53,43.78 92.61,43.53 | v91.26,57.75 v79.51,57.75 78.24,57.75 77.61,57.64
MCU_RD  (via drill 0.61 pad 1.02)
  Top 0.33: v95.39,40.61 94.75,40.61 94.75,33.3 94.43,32.99 94.43,29.81 94.75,29.5 94.75,23.78 94.43,23.46 v94.11,23.46 | v136.03,31.72 v136.03,33.62 | v136.03,23.46 v136.03,31.72 | v127.45,52.99 127.45,35.84 127.77,35.53 131.58,35.53 131.58,32.67 131.9,32.35 135.71,32.35 135.71,32.03 v136.03,31.72
  Bottom 0.33: v95.39,40.61 99.83,40.61 100.21,40.73 | v94.11,23.46 94.43,23.14 135.71,23.14 v136.03,23.46 | v136.03,33.62 136.03,35.15 136.03,38.38 163.33,38.38 163.65,38.7 163.65,40.61 163.97,40.61 164.28,40.92 164.6,40.92 164.6,41.56 164.92,42.2 | v136.03,31.72 137.29,31.72 137.29,29.69 | v127.45,52.99 127.14,52.67 115.39,52.67 115.07,52.99 113.02,52.99
MCU_RESE  (via drill 0.61 pad 1.02)
  Top 0.33: v168.09,62.52 167.78,62.83 167.78,72.04 167.46,72.36 165.55,72.36 164.92,72.67 | 76.33,36.8 75.7,37.11 75.38,37.43 75.38,37.75 v75.06,38.07 74.43,38.7 74.43,44.1 74.75,44.42 76.33,44.42 | v76.65,43.47 76.33,43.78 76.33,44.42 | 76.33,44.42 76.33,46.96 | v125.55,70.14 125.55,23.46 125.23,23.14 105.23,23.14 105.23,53.31 104.91,53.62 102.69,53.62 v102.69,52.67
  Bottom 0.33: v168.09,62.52 174.12,62.52 | v75.06,38.07 75.06,36.8 74.11,36.8 74.11,36.16 R14. | v76.65,43.47 76.97,43.15 80.14,43.15 80.46,42.83 85.54,42.83 85.86,42.51 88.72,42.51 88.72,43.15 88.61,43.53 | v125.55,70.14 133.8,70.14 134.12,69.82 135.71,69.82 135.71,71.41 136.03,71.72 136.03,72.04 136.34,72.04 136.66,72.36 138.25,72.36 138.25,70.45 138.56,70.45 138.88,70.14 138.88,69.82 139.2,69.82 139.52,69.5 141.42,69.5 141.74,69.18 154.76,69.18 154.76,70.45 155.07,70.45 155.39,70.77 160.47,70.77 160.79,71.09 161.43,71.09 161.74,71.41 163.33,71.41 163.33,71.72 163.65,72.04 164.6,72.04 164.92,72.67 | v102.69,52.67 102.37,52.35 101.42,52.35 101.1,52.04 101.1,51.4 100.78,51.4 100.47,51.09 93.16,51.09 92.84,51.4 85.54,51.4 85.22,51.09 85.22,50.13 84.91,50.13 84.59,49.81 83.64,49.81 83.32,49.5 83,49.5 83,47.27 79.83,47.27 79.51,46.96 76.33,46.96
MCU_WR  (via drill 0.61 pad 1.02)
  Top 0.33: v116.02,41.56 v116.02,46.32 | v132.85,43.47 132.53,43.15 v132.53,41.24 v132.53,33.62
  Bottom 0.33: v116.02,46.32 115.7,46.64 113.02,46.64 | 100.21,41.53 100.47,41.56 v116.02,41.56 116.34,41.24 v132.53,41.24 | 132.22,33.62 132.22,32.35 133.49,32.35 133.49,29.69 | 132.22,33.62 132.22,35.15 | v132.85,43.47 163.33,43.47 163.33,43.78 163.65,44.1 164.6,44.1 164.92,44.73 | v132.53,33.62 132.22,33.62
MEM_/CS1  (via drill 0.61 pad 1.02)
  Top 0.33: v120.47,55.21 120.47,37.11 v120.78,36.8 121.1,36.48 121.1,26.32 v122.06,26.32 | v153.49,26 v153.49,27.91
  Bottom 0.33: v120.78,36.8 122.06,36.8 122.06,35.01 | v120.47,55.21 120.15,55.53 113.02,55.53 | v153.49,26 122.37,26 v122.06,26.32 | v153.49,27.91 IC2.
MEM_CS2  (via drill 0.61 pad 1.02)
  Top 0.33: v152.22,31.4 v152.22,33.62
  Bottom 0.33: 150.95,29.68 150.95,29.18 152.22,29.18 152.22,29.68 v152.22,31.4 | v152.22,33.62 152.22,35.15
N$1
  Bottom 0.33: 174.12,70.14 174.44,70.77 175.4,70.77 175.71,71.09 175.71,71.41 177.3,71.41 177.62,71.72 177.94,71.72 177.94,75.53 156.66,75.53 156.02,74.92
N$2  (via drill 0.61 pad 1.02)
  Top 0.33: JP1. v77.92,29.18
  Bottom 0.33: v77.92,29.18 82.37,29.18 82.37,30.45 83.95,30.45 84.21,30.33
N$3  (via drill 0.61 pad 1.02)
  Top 0.33: v77.92,30.77 77.61,31.08 77.61,31.4 76.97,31.4 76.33,31.72
  Bottom 0.33: v77.92,30.77 78.24,31.08 83.95,31.08 84.21,31.13
N$4  (via drill 0.61 pad 1.02)
  Top 0.33: v113.8,33.62 113.8,62.52 114.12,62.83 v114.75,62.83
  Bottom 0.33: v113.8,33.62 100.47,33.62 100.21,33.53 | v114.75,62.83 116.34,62.83 116.66,62.52 116.66,60.93 123.96,60.93 124.28,60.61 124.28,57.75 130.63,57.75 130.94,58.07 131.58,58.07 131.9,58.39 135,58.39
N$5
  Top 0.33: 134.44,84.11 136.98,84.11 136.98,79.34 136.97,78.73
N$6
  Top 0.33: 134.44,81.56 134.44,79.34 134.43,78.73
N$7  (via drill 0.61 pad 1.02)
  Top 0.33: v143.33,72.99 143.33,81.56 144.6,81.56
  Bottom 0.33: v143.33,72.99 135.07,72.99 134.75,72.67 134.75,71.72 IC4.
N$8
  Bottom 0.33: 58.24,46.01 58.55,46.64 59.83,46.64 60.14,46.96 60.14,47.27 64.27,47.27 R4.
N$9  (via drill 0.61 pad 1.02)
  Top 0.33: v92.84,42.2 93.16,42.51 v93.16,48.55 Q1.
  Bottom 0.33: v92.84,42.2 91.89,42.2 91.89,43.15 91.81,43.53 | v93.16,48.55 92.21,48.55 91.58,48.56
N$10  (via drill 0.61 pad 1.02)
  Top 0.33: 88.4,48.55 88.4,50.45 88.08,50.77 88.08,53.94 | v88.4,45.37 88.4,48.55 | 88.4,48.55 v87.77,48.55
  Bottom 0.33: v88.4,45.37 88.72,45.05 90.62,45.05 90.94,44.73 90.94,43.78 91.01,43.53 | v87.77,48.55 88.72,48.55 89.35,48.56
N$11  (via drill 0.61 pad 1.02)
  Top 0.33: v137.61,36.8 v137.61,46.01
  Bottom 0.33: v137.61,46.01 141.74,46.01 141.74,46.96 143.91,46.96 | v137.61,36.8 137.29,36.48 137.29,35.15
N$12  (via drill 0.61 pad 1.02)
  Top 0.33: v148.09,31.72 v148.09,58.7
  Bottom 0.33: v148.09,58.7 148.41,58.39 153.41,58.39 | v148.09,31.72 140.15,31.72 139.84,31.4 138.56,31.4 IC5.
N$13
  Top 0.813: 83.64,76.8 83.64,74.58 67.44,74.58 53.79,74.58
N$14
  Bottom 0.33: 60.78,43.47 61.09,44.1 62.68,44.1 63,44.42 63,44.73 64.59,44.73 64.59,45.05 R5.
N$15
  Bottom 0.33: 58.24,43.47 58.55,42.83 59.83,42.83 60.14,42.51 60.14,42.2 64.59,42.2 64.59,42.83 R6.
N$16
  Bottom 0.33: 60.78,40.92 64.27,40.92 R7.
N$17  (via drill 0.61 pad 1.02)
  Top 0.33: v150.95,33.62 150.95,34.58 151.9,34.58 152.22,34.89 152.22,46.96 153.22,46.96
  Bottom 0.33: v150.95,33.62 150.63,33.3 136.98,33.3 136.66,32.99 136.66,32.67 134.12,32.67 133.8,32.99 133.49,32.99 133.49,35.15
N$18  (via drill 0.61 pad 1.02)
  Top 0.33: v26.49,52.99 20.14,52.99 v20.14,57.12
  Bottom 0.33: v26.49,52.99 25.54,52.99 24.5,52.85 | v20.14,57.12 18.23,57.12 18.23,56.8 14.74,56.8 14.42,56.48 14.42,52.35 15.69,52.35 16.33,52.37 16.96,52.35 17.91,52.35 18.35,52.04 18.23,52.67 18.23,53.62 R13.
N$19
  Bottom 0.33: 58.24,38.38 57.92,37.75 57.92,34.58 R8.
N$20
  Bottom 0.33: 50.62,38.38 50.3,37.75 50.3,34.58 R9.
N$21  (via drill 0.61 pad 1.02)
  Top 0.33: v26.49,49.5 25.54,49.5 v25.54,45.37
  Bottom 0.33: 16.33,47.61 16.96,47.59 17.91,47.59 18.35,47.6 | v26.49,49.5 25.54,49.5 24.5,49.66 | v25.54,45.37 25.22,45.05 18.23,45.05 18.23,46.96 18.35,47.6 | R16. 18.23,49.18 18.23,48.23 18.35,47.6
N$22
  Bottom 0.33: 21.29,49.82 21.73,50.45 23.63,50.45 24.5,50.45 25.54,50.45 27.44,50.45 27.76,50.13 27.76,46.32 26.8,46.32 26.49,46.01 26.49,44.42 14.42,44.42 | 14.42,44.42 14.42,43.15 19.18,43.15 19.5,42.83 19.5,41.24 22.04,41.24 22.68,41.2 | 14.42,44.42 14.42,48.86 14.74,49.18 15.69,49.18 16.33,49.49
N$23
  Bottom 0.33: 24.5,52.05 23.63,52.04 21.73,52.04 R15.
N$24
  Bottom 0.33: 58.24,48.55 60.78,48.55
N$25
  Bottom 0.33: 21.41,56.16 16.64,56.16 16.64,54.58 16.33,54.25 | 21.41,56.16 21.41,54.9 21.29,54.27 21.73,53.62 23.63,53.62 24.5,53.66 | 21.41,56.16 21.41,56.48 21.73,56.8 22.36,56.8 22.36,59.34 22.68,60
N$26
  Bottom 0.33: 24.5,48.85 23.63,48.86 22.68,48.86 22.36,48.55 21.41,48.55 21.41,48.23 R17.
N$27
  Top 0.33: 15.06,41.2 14.42,40.92 12.52,40.92 12.52,38.7 11.4,38.34
N$28
  Top 0.33: 15.06,60 14.42,59.66 13.79,59.66 13.79,53.62 13.47,53.31 12.52,53.31 11.4,52.7
N$29
  Bottom 0.33: 148.41,35.15 148.41,34.58 149.68,34.58 149.68,35.15
N$30  (via drill 0.61 pad 1.02)
  Top 0.33: v145.55,54.26 145.55,55.21 145.23,55.21 144.91,55.53 144.91,58.39 143.72,58.39 | v150,53.94 150,46.32 149.68,46.01 148.72,46.01 148.72,32.35 149.04,32.03 149.04,31.72 v149.36,31.4
  Bottom 0.33: v145.55,54.26 145.87,53.94 v150,53.94 | v149.36,31.4 149.68,31.08 149.68,29.68
N$31
  Bottom 0.33: 28.71,60.6 28.07,60.61 27.12,60.61 27.12,57.75 27.25,56.7
N$32
  Bottom 0.33: 39.68,65.95 40.46,66.01 45.54,66.01 46.26,65.96
N$33
  Top 0.406: JP2. 2.67,69.5
  Bottom 0.33: 2.67,69.5 JP2.
  Bottom 0.406: 6.8,65.69 5.21,65.69 5.21,69.5 2.67,69.5
N$34
  Bottom 0.33: 147.14,29.18 148.41,29.18 148.41,29.68 | 147.14,29.18 147.14,27.91 134.75,27.91 134.75,29.69 | 147.14,29.18 147.14,29.68
N$35
  Bottom 0.406: T1. 2.7,64.42 2.67,64.42 2.67,67.28
N$36
  Bottom 0.33: R29. 28.71,13.3 28.71,14.89 SW1.
N$37
  Bottom 0.406: 3.67,62.13 3.67,62.2 R24.
N$38
  Bottom 0.33: R30. 44.27,13.3 44.27,14.89 SW2.
N$39
  Bottom 0.33: R31. 60.14,13.3 60.14,14.89 SW3.
N$40
  Bottom 0.33: R32. 76.02,13.3 76.02,14.89 SW4.
N$41
  Bottom 0.33: R33. 91.58,13.3 91.58,14.89 SW5.
N$42
  Bottom 0.33: R34. 107.45,13.3 107.45,14.89 SW6.
N$43
  Bottom 0.33: R35. 123.33,13.3 123.33,14.89 SW7.
N$44
  Bottom 0.33: R36. 138.88,13.3 138.88,14.89 SW8.
PER_RD  (via drill 0.61 pad 1.02)
  Top 0.33: v95.7,32.67 95.7,25.05 96.02,24.73 100.47,24.73 v100.47,27.59 | v112.85,27.59 112.85,66.96 113.17,67.28 117.61,67.28 v117.61,61.88 | v121.74,61.88 v121.74,70.77 | v172.85,74.58 172.85,69.5 173.17,69.18 173.17,68.55 173.49,68.23 173.49,67.91 174.12,67.59
  Bottom 0.33: v95.7,32.67 84.59,32.67 84.21,32.73 | v100.47,27.59 v112.85,27.59 | v117.61,61.88 v121.74,61.88 | v121.74,70.77 121.74,73.63 142.69,73.63 143.01,73.94 153.81,73.94 154.12,73.63 156.66,73.63 156.98,73.94 157.62,73.94 157.93,74.26 160.47,74.26 160.79,74.58 v172.85,74.58
PER_WR  (via drill 0.61 pad 1.02)
  Top 0.33: v110.31,28.54 v110.31,25.05 | v166.82,25.68 166.82,60.29 167.14,60.61 167.14,68.55 v166.82,68.87
  Bottom 0.33: v110.31,28.54 109.99,28.86 99.19,28.86 99.19,29.81 98.88,29.81 98.56,30.13 98.56,33.3 98.24,33.62 84.59,33.62 84.21,33.53 | v110.31,25.05 110.62,25.37 152.85,25.37 153.17,25.05 161.11,25.05 161.43,25.37 161.43,25.68 v166.82,25.68 | v166.82,68.87 174.76,68.87 175.08,68.55 175.4,68.55 175.71,68.23 176.35,68.23 176.66,67.59
RESET  (via drill 0.61 pad 1.02)
  Top 0.33: v55.7,47.27 55.7,52.99 55.7,53.62
  Bottom 0.33: 28.61,40.28 29.03,40.29 32.52,40.29 32.52,40.61 32.56,41.24 32.84,41.88 32.84,43.15 32.85,44.2 32.84,45.05 32.84,45.69 40.77,45.69 40.77,46.32 41.09,46.32 41.41,46.64 41.73,46.64 42.05,46.96 42.36,46.96 42.68,47.27 v55.7,47.27
SCL  (via drill 0.61 pad 1.02)
  Top 0.33: v96.02,46.01 96.02,56.48 95.7,56.8 95.7,58.07 95.39,58.39 95.39,59.34 95.7,59.66 97.29,59.66 v97.29,65.37 | v59.51,65.37 59.19,65.06 v59.19,59.66 | v36.01,52.04 36.33,52.35 v36.33,58.07
  Bottom 0.33: v96.02,46.01 95.7,46.01 95.7,43.78 95.81,43.53 | v59.51,65.37 v97.29,65.37 | v59.19,59.66 56.33,59.66 55.7,59.78 55.06,59.34 55.06,58.39 54.74,58.07 | v36.01,52.04 36.97,52.04 38,52.05 | v36.33,58.07 54.74,58.07 | 54.74,58.07 55.38,58.07 55.38,56.8 55.7,56.16
SDA  (via drill 0.61 pad 1.02)
  Top 0.33: v96.97,45.05 97.29,45.37 97.29,53.94 96.97,54.26 96.97,56.8 96.66,57.12 96.34,57.12 v96.34,58.7 | v40.14,51.72 v40.14,59.66
  Bottom 0.33: v96.97,45.05 96.66,45.05 96.66,43.78 96.61,43.53 | v96.34,58.7 86.18,58.7 85.86,58.39 80.14,58.39 79.83,58.7 60.46,58.7 | 60.46,58.7 60.14,59.02 60.14,60.93 54.11,60.93 53.79,60.61 53.79,60.29 53.16,59.78 52.52,59.66 v40.14,59.66 | v40.14,51.72 40.14,51.4 38.87,51.4 38,51.26 | 60.46,58.7 56.97,58.7 56.97,55.85 56.65,55.53 56.65,55.21 56.33,55.21 56.02,54.9 55.06,54.9 55.06,54.58 54.74,54.26 53.48,54.26 53.16,53.62
SIC  (via drill 0.61 pad 1.02)
  Top 0.33: v95.07,49.5 v95.07,42.2 | v84.59,45.37 v84.59,48.86 | v69.35,39.02 v69.35,45.69
  Bottom 0.33: v95.07,42.2 95.07,43.15 95.01,43.53 | v95.07,49.5 85.22,49.5 84.91,49.18 84.59,49.18 v84.59,48.86 | v84.59,45.37 74.75,45.37 74.43,45.69 v69.35,45.69 | v69.35,39.02 60.46,39.02 60.14,39.34 60.14,39.97 59.83,40.29 58.55,40.29 58.24,40.92
SID  (via drill 0.61 pad 1.02)
  Top 0.33: v94.11,41.24 94.11,52.99 94.43,53.31 94.43,59.98 94.11,60.29 v94.11,64.42 | v57.6,67.28 57.92,66.96 57.92,65.37 57.6,65.06 57.6,57.12 57.28,56.8 56.97,56.8 56.97,53.31 56.65,52.99 56.65,52.67 56.33,52.35 56.33,47.91 56.65,47.59 56.65,46.96 56.33,46.64 56.33,41.24 55.7,40.92
  Bottom 0.33: v94.11,41.24 94.11,43.15 94.21,43.53 | v94.11,64.42 94.43,64.74 96.02,64.74 96.34,64.42 97.92,64.42 98.24,64.74 98.24,67.28 v57.6,67.28
SOC
  Bottom 0.33: 35.25,44.2 35.38,44.73 45.85,44.73 46.17,44.42 46.49,44.42 46.81,44.1 47.12,44.1 47.44,43.78 47.76,43.78 47.76,42.83 49.98,42.83 50.3,42.51 50.3,41.56 50.62,40.92
SOD
  Bottom 0.33: 34.45,44.2 34.42,43.15 34.42,42.51 42.36,42.51 42.68,42.2 45.85,42.2 46.17,41.88 47.12,41.88 47.44,41.56 47.76,41.56 48.08,40.92
SOI
  Bottom 0.33: 33.65,44.2 33.79,43.15 33.79,39.02 44.59,39.02 44.9,39.34 44.9,39.66 45.85,39.66 46.17,39.34 46.49,39.34 46.81,39.02 47.76,39.02 48.08,38.38
TASTER0  (via drill 0.61 pad 1.02)
  Top 0.33: v88.08,25.05 v88.08,28.86 | v21.41,26.64 21.41,24.1 21.09,23.78 10.61,23.78 10.61,26.32 10.29,26.64 10.29,26.95 9.98,27.27 9.98,27.91 9.34,28.23
  Bottom 0.33: v88.08,28.86 88.72,28.86 88.72,27.91 88.61,27.53 | v88.08,25.05 87.77,25.37 82.05,25.37 81.73,25.68 70.3,25.68 69.67,26.32 44.59,26.32 43.95,26.95 21.73,26.95 v21.41,26.64
TASTER1  (via drill 0.61 pad 1.02)
  Top 0.33: v83,24.41 v83,26.95 | v22.36,25.68 22.04,25.37 22.04,23.46 21.73,23.14 9.34,23.14 9.34,25.68
  Bottom 0.33: v83,26.95 83.32,26.64 89.35,26.64 89.35,27.27 89.41,27.53 | v83,24.41 82.69,24.73 81.73,24.73 81.42,25.05 69.98,25.05 69.35,25.68 v22.36,25.68
TASTER2  (via drill 0.61 pad 1.02)
  Top 0.33: v72.21,32.99 v72.21,28.54
  Bottom 0.33: v72.21,28.54 72.21,27.59 72.53,27.27 79.51,27.27 79.51,27.59 79.83,27.91 84.91,27.91 85.22,28.23 85.54,28.23 85.86,28.54 85.86,29.5 86.18,29.81 90.31,29.81 90.31,27.91 90.21,27.53 | v72.21,32.99 56.97,32.99 56.65,33.3 56.65,35.53 52.52,35.53 52.2,35.21 51.89,35.21 51.89,32.99 44.59,32.99 44.27,33.3 27.44,33.3 27.12,32.99 26.49,32.99 26.17,32.67 25.85,32.67 25.85,30.77 14.11,30.77 13.79,30.45 13.79,30.13 12.52,30.13 12.2,29.81 12.2,28.86 11.88,28.23
TASTER3  (via drill 0.61 pad 1.02)
  Top 0.33: v46.49,33.94 v46.49,27.27
  Bottom 0.33: v46.49,27.27 70.3,27.27 70.3,26.64 70.62,26.32 82.05,26.32 82.37,26 90.94,26 90.94,27.27 91.01,27.53 | v46.49,33.94 14.11,33.94 13.79,33.62 13.79,31.4 13.47,31.4 13.15,31.08 13.15,30.77 10.93,30.77 10.61,30.45 10.61,26.32 11.56,26.32 11.88,25.68
TASTER4  (via drill 0.61 pad 1.02)
  Top 0.33: v91.26,29.18 89.03,29.18 89.03,29.5 88.72,29.81 83.95,29.81 83.95,23.46 83.64,23.14 69.03,23.14 v69.03,24.73 | v45.54,29.81 v45.54,24.73
  Bottom 0.33: v91.26,29.18 91.89,29.18 91.89,27.91 91.81,27.53 | v69.03,24.73 68.72,25.05 45.85,25.05 v45.54,24.73 | v45.54,29.81 21.41,29.81 21.09,30.13 15.06,30.13 14.74,29.81 14.74,28.86 14.42,28.23
TASTER5  (via drill 0.61 pad 1.02)
  Top 0.33: v85.54,30.77 81.73,30.77 81.73,24.41 81.42,24.1 v81.1,24.1 | v47.44,34.89 v47.44,24.1 | v15.69,34.89 15.69,27.59 15.38,27.27 15.38,26.95 15.06,26.64 15.06,26 14.42,25.68
  Bottom 0.33: v85.54,30.77 92.53,30.77 92.53,27.91 92.61,27.53 | v81.1,24.1 80.78,23.78 49.66,23.78 49.35,24.1 49.35,24.41 47.76,24.41 v47.44,24.1 | v15.69,34.89 v47.44,34.89
TASTER6  (via drill 0.61 pad 1.02)
  Top 0.33: v92.21,26.32 92.21,36.8 91.89,37.11 91.89,37.43 90.31,37.43 90.31,45.37 89.99,45.69 89.35,45.69 89.35,59.98 89.03,60.29 v89.03,66.33 | 16.96,28.23 v16.96,64.1
  Bottom 0.33: v92.21,26.32 93.48,26.32 93.48,27.27 93.41,27.53 | v89.03,66.33 58.87,66.33 58.55,66.01 58.55,64.42 48.4,64.42 48.08,64.1 48.08,63.78 17.28,63.78 v16.96,64.1
TASTER7  (via drill 0.61 pad 1.02)
  Top 0.33: v48.71,23.46 48.4,23.78 48.4,35.53 48.08,35.84 45.54,35.84 45.54,31.08 45.22,30.77 44.59,30.77 v44.59,27.59
  Bottom 0.33: v48.71,23.46 49.03,23.14 89.03,23.14 89.03,25.05 89.35,25.37 94.11,25.37 94.11,27.27 94.21,27.53 | v44.59,27.59 20.77,27.59 20.45,27.27 20.45,26.95 18.87,26.95 18.55,26.64 18.23,26.64 17.91,26.32 17.28,26.32 16.96,25.68
TASTERX0
  Bottom 0.33: 31.88,13.19 32.52,12.67 34.74,12.67 35.06,12.35 35.05,11.35 34.42,12.03 27.12,12.03 27.12,14.57 26.8,14.89 9.98,14.89 9.98,13.62 9.53,12.98
TASTERX1  (via drill 0.61 pad 1.02)
  Top 0.33: v50.94,8.54 50.94,10.45 50.8,11.35
  Bottom 0.33: 47.44,13.19 48.08,12.67 50.3,12.67 50.62,12.35 50.8,11.35 | v50.94,8.54 9.98,8.54 9.98,9.81 9.53,10.45
TASTERX2  (via drill 0.61 pad 1.02)
  Top 0.33: v12.2,15.84 12.2,13.62 12.06,12.98 | v27.12,15.84 27.12,13.94 27.44,13.62 v33.47,13.62
  Bottom 0.33: 63,13.19 63.64,12.67 66.17,12.67 66.49,12.35 66.5,11.35 65.86,12.03 58.55,12.03 58.55,13.3 58.24,13.62 50.62,13.62 50.62,13.94 50.3,14.26 45.85,14.26 45.85,12.03 42.68,12.03 42.68,13.3 42.36,13.62 v33.47,13.62 | v12.2,15.84 v27.12,15.84
TASTERX3  (via drill 0.61 pad 1.02)
  Top 0.33: v12.2,4.41 12.2,9.81 12.06,10.45 | v82.37,4.41 82.37,10.45 82.28,11.35
  Bottom 0.33: 78.88,12.87 79.51,12.35 82.37,12.35 82.28,11.35 | v12.2,4.41 v82.37,4.41
TASTERX4  (via drill 0.61 pad 1.02)
  Top 0.33: v7.44,3.46 7.44,16.8 13.79,16.8 14.11,16.48 14.11,13.3 14.61,12.98 | v97.92,8.54 97.92,10.45 98.03,11.35
  Bottom 0.33: 94.75,13.19 95.39,12.67 97.61,12.67 97.92,12.35 98.03,11.35 | v7.44,3.46 16.64,3.46 16.96,3.78 81.73,3.78 82.05,3.46 85.54,3.46 85.86,3.78 85.86,8.22 92.53,8.22 92.84,8.54 v97.92,8.54
TASTERX5  (via drill 0.61 pad 1.02)
  Top 0.33: v47.76,7.59 47.76,1.87 15.06,1.87 14.74,2.19 14.74,9.81 14.61,10.45 | v90.31,9.18 96.02,9.18 96.02,13.3 v96.34,13.62
  Bottom 0.33: 110.31,13.19 110.94,12.67 113.48,12.67 113.8,12.35 113.75,11.35 113.17,12.03 105.86,12.03 105.86,13.3 105.55,13.62 v96.34,13.62 | v47.76,7.59 59.83,7.59 60.14,7.91 60.14,8.22 60.78,8.22 61.09,8.54 85.22,8.54 85.54,8.86 89.99,8.86 v90.31,9.18
TASTERX6  (via drill 0.61 pad 1.02)
  Top 0.33: v129.68,3.14 129.68,10.45 129.55,11.35
  Bottom 0.33: 126.18,12.87 126.82,12.35 129.36,12.35 129.55,11.35 | v129.68,3.14 92.53,3.14 92.53,4.41 92.21,4.41 91.89,4.73 87.13,4.73 87.13,2.19 86.81,1.87 6.49,1.87 6.49,4.09 6.8,4.41 7.44,4.41 7.44,10.76 7.76,10.76 8.07,11.08 8.39,11.08 8.39,11.4 8.71,11.71 15.38,11.71 15.38,12.03 15.69,12.03 16.01,12.35 16.96,12.35 17.14,12.98
TASTERX7  (via drill 0.61 pad 1.02)
  Top 0.33: v17.28,2.83 17.28,9.81 17.14,10.45 | v90.62,5.68 90.94,5.37 90.94,5.05 91.58,5.05 91.58,4.41 91.89,4.09 v93.48,4.09
  Bottom 0.33: 142.06,12.87 142.69,12.35 145.23,12.35 145.25,11.35 144.91,10.45 144.91,4.73 144.6,4.41 93.8,4.41 v93.48,4.09 | v17.28,2.83 86.18,2.83 86.5,3.14 86.5,5.68 v90.62,5.68
VCC  (via drill 0.61 pad 1.02)
  Top 0.33: DIS1. 177.3,50.13 178.57,50.13 178.57,69.5 178.25,69.82 177.3,69.82 176.66,70.14 | 144.6,46.96 v145.55,46.96 | 144.6,46.96 IC14. 141.42,46.96 141.42,47.27 141.1,47.59 141.1,47.91 v140.79,48.23 141.1,48.55 141.1,62.2 v141.42,62.52 | 144.6,46.96 v144.6,30.13 144.91,29.81 v144.91,26.95 | 19.5,28.23 18.87,28.54 18.87,65.06 18.55,65.37 17.6,65.37 16.96,65.69 | v75.38,43.47 75.38,42.83 75.06,42.51 75.06,39.66 75.7,39.66 76.33,39.34 | v71.25,54.58 v71.25,41.56 70.94,41.24 v70.94,28.54 | v111.89,66.33 112.21,66.01 112.21,28.23 111.89,27.91 111.89,26.95 112.21,26.64 v114.75,26.64 v114.75,42.83 v114.75,45.69 115.07,46.01 115.07,52.04 118.25,52.04 118.56,52.35 v118.56,62.83 | v89.35,41.56 89.67,41.24 v89.67,31.72
  Top 0.813: 36.33,84.74 L1. 53.79,79.98 73.48,79.98 | 73.48,79.98 73.48,76.8 | 73.48,79.98 77.08,79.98 | 36.33,84.74 36.33,82.83 | 36.33,84.74 26.17,84.74 26.17,75.22
  Bottom 0.33: 128.72,62.52 128.72,61.24 128.77,60.45 | 128.72,62.52 v141.42,62.52 146.5,62.52 146.5,61.24 146.55,60.45 | v140.79,48.23 136.34,48.23 136.34,46.96 IC3. | v145.55,46.96 IC12. 156.34,46.96 156.66,46.64 160.47,46.64 160.79,46.32 161.43,46.32 161.74,46.01 176.35,46.01 176.35,49.18 DIS1. | v144.6,30.13 145.87,30.13 145.87,29.68 | v144.91,26.95 162.38,26.95 | 26.17,66.01 28.71,66.01 29.52,65.95 | R27. 65.54,54.58 v71.25,54.58 74.43,54.58 R28. 75.7,54.58 76.97,54.58 R26. | 74.11,40.61 74.11,41.24 73.32,41.67 | 74.11,40.61 74.11,39.02 73.32,38.59 | v75.38,43.47 75.38,42.83 74.43,42.83 74.11,42.51 74.11,42.2 73.32,41.67 | 89.35,41.88 89.35,43.15 89.41,43.53 | 89.35,41.88 85.22,41.88 84.91,42.2 80.14,42.2 79.83,41.88 79.03,41.36 78.24,40.92 78.24,40.61 74.11,40.61 | v71.25,41.56 72.53,41.56 73.32,41.67 | 115.7,26.64 115.7,27.59 | 115.7,26.64 115.7,26.32 115.39,26 109.36,26 109.36,25.05 109.04,24.73 95.7,24.73 95.7,27.27 95.81,27.53 95.7,27.91 95.7,31.08 95.39,31.4 89.99,31.4 v89.67,31.72 | 115.7,27.59 115.7,29.5 | 115.7,27.59 121.1,27.59 121.42,27.91 123.01,27.91 123.33,27.59 130.94,27.59 130.94,29.69 | v114.75,45.69 114.75,45.37 113.02,45.37 | v114.75,42.83 113.02,42.83 | v111.89,66.33 109.36,66.33 108.92,67.12 | 115.7,26.64 v114.75,26.64 | 89.35,41.88 v89.35,41.56 | v70.94,28.54 44.27,28.54 43.95,28.23 19.5,28.23 | 128.72,62.52 128.72,63.15 124.28,63.15 123.96,62.83 v118.56,62.83
  Bottom 0.406: 26.17,75.22 26.17,66.01 26.17,65.69 16.96,65.69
